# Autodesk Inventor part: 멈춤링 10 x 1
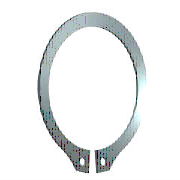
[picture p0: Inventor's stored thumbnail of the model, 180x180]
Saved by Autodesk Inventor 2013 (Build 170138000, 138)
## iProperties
IsCustomPart: 0
Company: 한국ATC센터
Created: 2014-07
Part Number: 멈춤링 10 x 1
Material: Steel, Mild
Description: 리테이닝 링(C형)
Document SubType Name: Modeling
Standard: KS B 1336
Designer: KYOUNG IL JANG
Standards Organization: KS
Language: ko-KR
Size Designation: 10 x 1
Categories: <MemberInstance><Categories><Category DisplayName="샤프트 부품" InternalName="7f7aeb1f-a693-4053-b835-cee3144e0d98" Mnemonic="SHFT"><Category DisplayName="써클립" Inter
Density: 7.86 g/cm^3
Mass: 0.423087 g
Surface Area: 1.9243 cm^2
Volume: 0.0538279 cm^3
Author: KYOUNG IL JANG
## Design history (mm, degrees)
sketch "스케치1"
  geometry: L1 (-6, 0)-(6, 0) reference; L2 (0, 20.189)-(0, -80.536) reference; L3 (-48.09, 0)-(48.09, 0) reference; L4 (-0.3, -9.791)-(-0.3, -12.791); L5 (-0.3, -6.54)-(-0.3, -13.29); L6 (-2.795, 1.6)-(3.672, 1.6); L7 (0.3, -6.54)-(0.3, -13.29); L8 (0.3, -9.791)-(0.3, -12.791); C1 r 0.6 at (-1.2, -11.486); C2 r 0.6 at (1.2, -11.486); A1 r 4.8 centre (0, -5) between (0.3, -9.791) and (-0.3, -9.791); A2 r 6.2 centre (0, -4.6) between (2.988, -10.033) and (-2.988, -10.033); A3 r 7.796 centre (0, -5) between (-1.418, -12.666) and (-0.3, -12.791); A4 r 1.2 centre (-1.2, -11.486) between (-2.383, -11.285) and (-1.418, -12.666); A5 r 1.2 centre (-3.566, -11.084) between (-2.383, -11.285) and (-2.988, -10.033); A6 r 1.2 centre (3.566, -11.084) between (2.988, -10.033) and (2.383, -11.285); A7 r 1.2 centre (1.2, -11.486) between (1.418, -12.666) and (2.383, -11.285); A8 r 7.796 centre (0, -5) between (0.3, -12.791) and (1.418, -12.666)
  constraints: 16 point on circle, 12 end point, 10 centre point, 9 symmetric about line, 5 point on line, 4 tangent, 3 coincident, 2 horizontal, 1 perpendicular, 1 vertical, 5 other
  dimensions: "d0" = 9.6 diameter of A1 (= ND); "d1" = 3 distance of L4.end L4.start (= SRB2); "d6" = 0.3 distance between parallel lines of L2 L5 (= 0.25 x SD5); "d7" = 1.6 distance between parallel lines of L6 L3 (= SRB1); "d8" = 0.4 distance of A1.centre A2.centre (= 0.25 x SRB1); "d9" = 1.2 radius of A4 (= SD5); "d10" = 1.2 radius of A5 (= SD5); "d11" = 0.9 distance from line of L4 A4.centre (= 0.75 x SD5); "d12" = 1.2 diameter of C1 (= SD5); "d13" = 1.2 diameter of C2 (= SD5); "d14" = 5 distance from line of A1.centre L1 (= 0.5 x WD)
extrude "본체" new body sketch "스케치1" distance "d2" = 1 (= SD); taper "d3" = 0 deg
workaxis "Work Axis1"
workplane "Work Plane1"
body "Solid1"
other parameters: "SD" = 1 [user parameter; used in 1 equation term], "SRB1" = 1.6 [user parameter; used in 2 equation terms], "ND" = 9.6 [user parameter; used in 1 equation term], "SRB2" = 3 [user parameter; used in 1 equation term], "SD5" = 1.2 [user parameter; used in 6 equation terms], "d15" = 0, "d16" = 0, "d17" = 0, "d41" = 0, "d42" = 0, "SD3" = 9.3 [user parameter], "WDMAX" = 11 [user parameter]
